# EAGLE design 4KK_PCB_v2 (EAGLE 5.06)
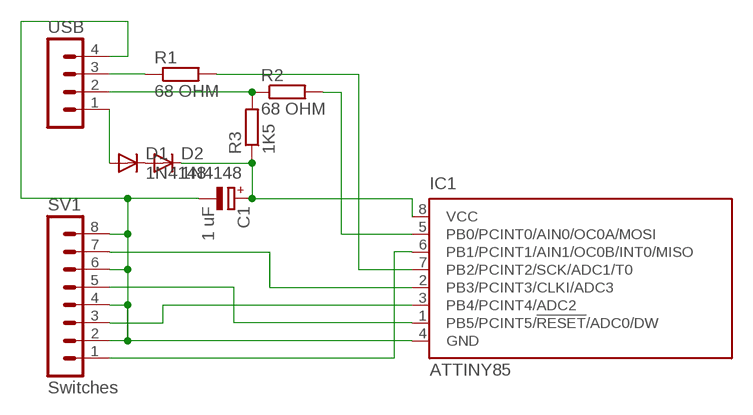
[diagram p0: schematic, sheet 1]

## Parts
C1  1 uF  CPOL-EUE2.5-5  [E2,5-5]
D1  1N4148  1N4148DO35-7  [DO35-7]
D2  1N4148  1N4148DO35-7  [DO35-7]
IC1  ATTINY85  TINY85-20PU  [DIL08]
R1  68 OHM  R-EU_0309/10  [0309/10]
R2  68 OHM  R-EU_0309/10  [0309/10]
R3  1K5  R-EU_0309/10  [0309/10]
SV1  Switches  MA08-1  [MA08-1]
USB  MA04-1  [MA04-1]

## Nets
D+: R1.1 USB.3
D-: R2.1 R3.2 USB.2
GND: C1.- IC1.4(GND) SV1.2 SV1.4 SV1.6 SV1.8 USB.4
N$3: D1.C D2.A
N$4: C1.+ D2.C IC1.8(VCC) R3.1
N$5: IC1.6(PB1/PCINT1/AIN1/OC0B/INT0/MISO) SV1.1
N$8: IC1.7(PB2/PCINT2/SCK/ADC1/T0) R1.2
N$9: IC1.5(PB0/PCINT0/AIN0/OC0A/MOSI) R2.2
N$10: IC1.3(PB4/PCINT4/ADC2) SV1.3
N$11: IC1.1(PB5/PCINT5/!RESET!/ADC0/DW) SV1.5
N$12: IC1.2(PB3/PCINT3/CLKI/ADC3) SV1.7
V+: D1.A USB.1

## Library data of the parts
C1 = rcl:CPOL-EU: POLARIZED CAPACITOR, European symbol
D1 D2 = diode:1N4148: DIODE
IC1 = attiny85:TINY85: 8-bit AVR Microcontroller with 1K Bytes In-System Programmable Flash Source: http://www.atmel.com/dyn/resources/prod_documents/2535S.pdf
R1-R3 = resistor:R-EU_: RESISTOR, European symbol
SV1 = con-lstb:MA08-1: PIN HEADER
USB = con-lstb:MA04-1: PIN HEADER

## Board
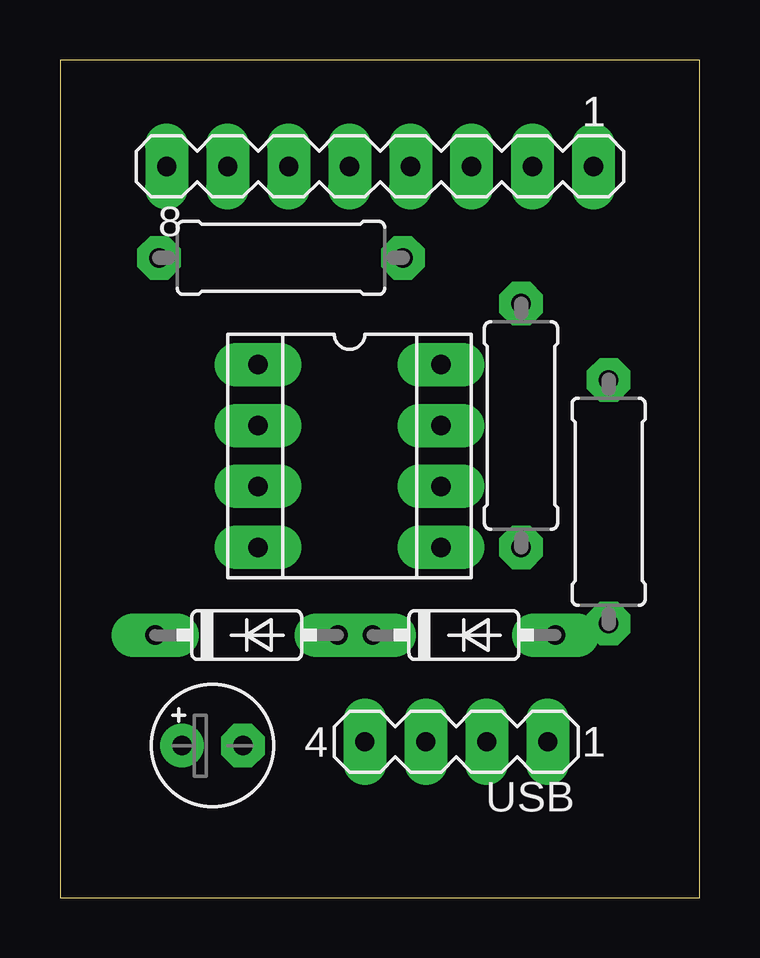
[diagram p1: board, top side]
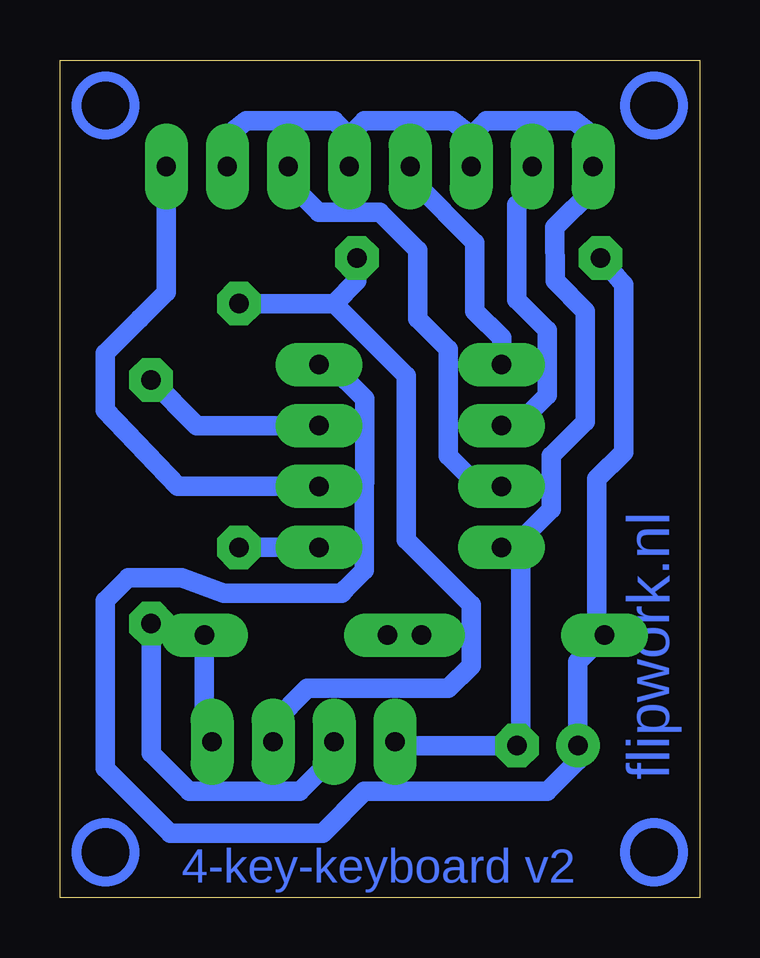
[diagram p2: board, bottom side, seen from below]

Size 26.66 x 34.91 mm. Coordinates in mm from the lower left corner, seen from the top.
Outline: 0,0 26.66,0 26.66,34.91 0,34.91 0,0
Copper layers (1*16): Top 0.035mm / dielectric 1.5mm / Bottom 0.035mm
Design rules "FJ043CWRTMEP27Y3QS *": minimum track width 0.8mm, minimum drill 0.8mm, track to track 0.6mm, track to pad 0.6mm, pad to pad 0.35mm, via to via 0.6mm, smd to smd 8mil, copper to edge 10mil, drill to drill 8mil, minimum pad ring 0.5mm, minimum via ring 0.45mm, stop-mask expansion 0mil, vias tented up to drill 0mil, thermal gap 10mil

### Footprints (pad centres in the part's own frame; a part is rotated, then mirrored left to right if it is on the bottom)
E2,5-5 = drill 0.813 pad 1.6 round: + -1.27,0 | drill 0.813 pad 1.6 octagon: - 1.27,0
DO35-7 = drill 0.813 long: A 3.81,0; C -3.81,0
DIL08 = drill 0.813 long: 1 -3.81,-3.81; 2 -1.27,-3.81; 3 1.27,-3.81; 4 3.81,-3.81; 5 3.81,3.81; 6 1.27,3.81; 7 -1.27,3.81; 8 -3.81,3.81
0309/10 = drill 0.813 octagon: 1 -5.08,0; 2 5.08,0
MA08-1 = drill 0.8 long: 1 -8.89,0; 2 -6.35,0; 3 -3.81,0; 4 -1.27,0; 5 1.27,0; 6 3.81,0; 7 6.35,0; 8 8.89,0
MA04-1 = drill 0.8 long: 1 -3.81,0; 2 -1.27,0; 3 1.27,0; 4 3.81,0

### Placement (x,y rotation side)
C1  6.35,6.35 0 top
D1  16.83,10.95 0 top
D2  7.78,10.95 0 top
IC1  12.06,18.41 270 top
R1  22.86,16.51 90 top
R2  19.21,19.68 270 top
R3  9.21,26.67 0 top
SV1  13.34,30.48 180 top
USB  16.51,6.51 180 top

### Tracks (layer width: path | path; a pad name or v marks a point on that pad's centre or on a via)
D+
  Bottom 0.813: USB.3 15.24,5.87 16.67,4.45 21.27,4.45 22.86,6.03 R1.1
D-
  Bottom 0.813: 18.57,24.77 R2.1 15.24,24.77 | 15.24,24.77 12.22,21.75 12.22,14.92 9.53,12.22 9.53,9.68 10.48,8.73 16.35,8.73 17.78,7.3 USB.2 | 15.24,24.77 14.29,25.72 R3.2
GND
  Bottom 0.813: SV1.2 19.68,31.75 18.89,32.38 15.24,32.38 14.61,31.75 | 14.61,31.75 SV1.4 | 9.53,31.75 10.32,32.38 13.97,32.38 14.61,31.75 | 9.53,31.75 SV1.6 | 9.53,31.75 8.89,32.38 5.24,32.38 4.45,31.75 SV1.8 4.45,29.53 6.03,27.94 6.03,25.72 4.76,24.45 4.76,19.84 6.19,18.41 6.19,16.19 7.62,14.76 7.78,14.61 IC1.4 7.46,13.81 7.46,6.51 C1.- 12.38,6.35 USB.4
N$3
  Bottom 0.813: D2.A 11.75,10.95 D1.C
N$4
  Bottom 0.813: D2.C 5.08,9.84 C1.+ 5.08,5.71 6.35,4.45 13.97,4.45 15.72,2.7 22.07,2.7 24.77,5.4 24.77,12.38 23.81,13.34 21.59,13.34 19.84,12.7 14.92,12.7 14.76,12.86 13.97,13.65 13.97,20.8 15.4,22.23 IC1.8 | D2.C | R3.1 3.17,25.56 3.17,18.57 4.29,17.46 4.29,11.27 D2.C
N$5
  Bottom 0.813: SV1.1 22.23,30.16 22.23,28.26 22.23,25.24 23.34,24.13 24.77,22.7 24.77,20.32 21.75,17.14 IC1.6
N$8
  Bottom 0.813: IC1.7 20.95,19.68 R1.2
N$9
  Bottom 0.813: IC1.5 R2.2
N$10
  Bottom 0.813: IC1.3 9.21,17.14 10.48,18.41 10.48,22.86 11.75,24.13 11.75,26.99 13.34,28.57 15.88,28.57 17.14,29.84 SV1.3
N$11
  Bottom 0.813: IC1.1 8.26,23.34 9.37,24.45 9.37,27.3 11.91,29.84 12.06,30 12.06,30.32 SV1.5
N$12
  Bottom 0.813: IC1.2 7.62,19.68 6.35,20.95 6.35,23.65 7.62,24.92 7.62,28.89 6.99,29.53 SV1.7
V+
  Bottom 0.813: USB.1 20.32,6.99 20.32,6.83 20.64,7.3 D1.A
(copper drawn outside any net)
  shapes: Bottom circle x4

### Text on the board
Bottom: flipwork.nl | 4-key-keyboard v2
